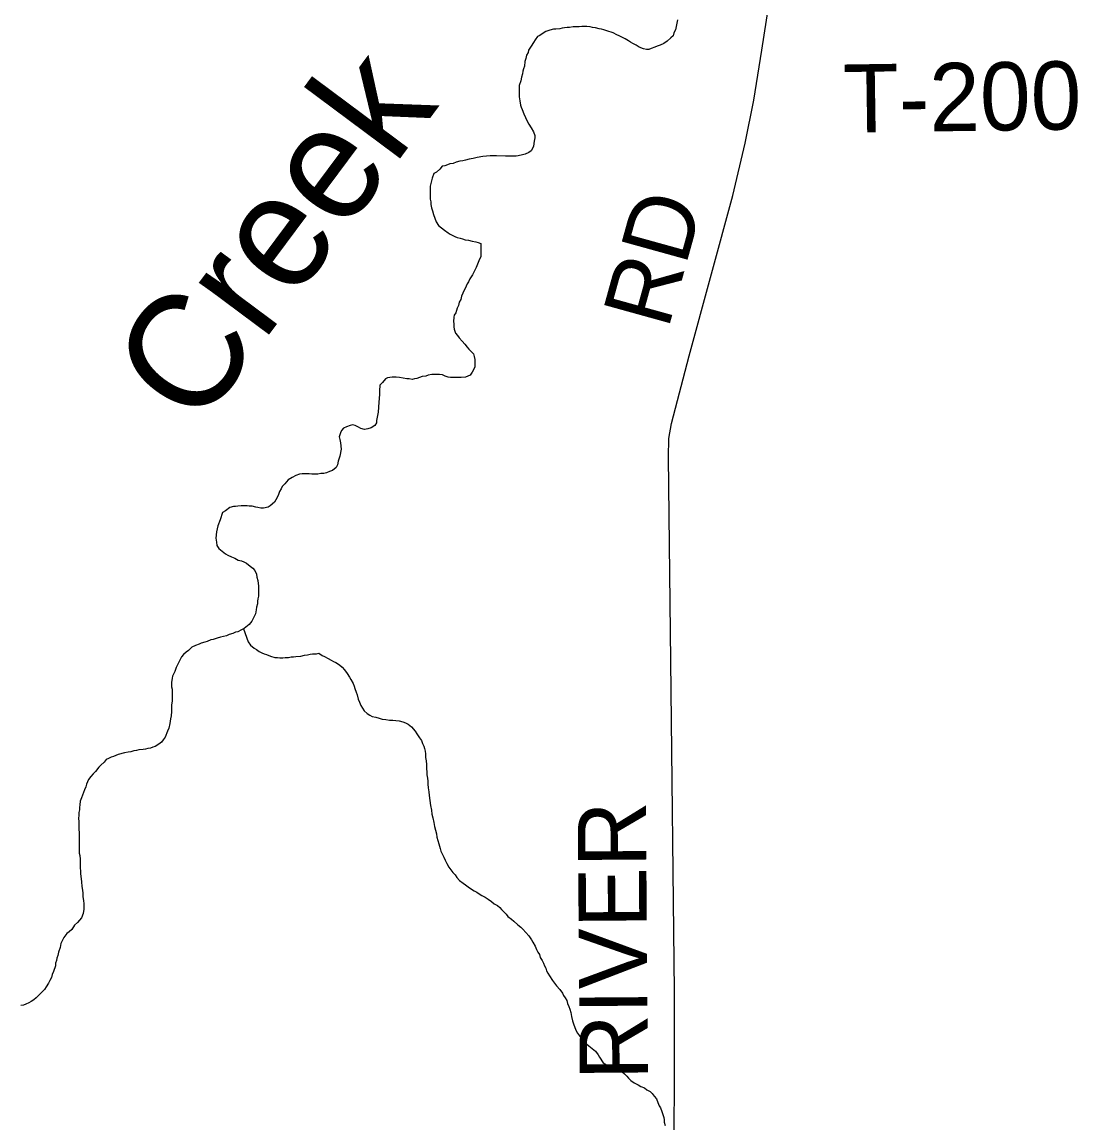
# Model space of a CAD drawing. Extents: x 0 to 34, y 0 to 22.
# Drawn here: x 3.195 to 4.075, y 18.8 to 19.717 of the extents above; entities that cross this region are included whole.
import ezdxf

# ---------------------------------------------------------------- set-up
doc = ezdxf.new("R2010")
doc.units = 0
for name, color, linetype in [('GM_X_Minor_River', 7, 'Continuous'), ('GM_X_Minor_River_Text', 7, 'Continuous'), ('GM_X_Township_Road', 7, 'Continuous'), ('GM_X_Township_Road_Text', 7, 'Continuous')]:
    doc.layers.add(name, color=color, linetype=linetype)

msp = doc.modelspace()

# ---------------------------------------------------------------- linework, layer by layer
at = {"layer": 'GM_X_Minor_River'}
for points in [[(3.74103, 19.71925), (3.73912, 19.71088), (3.73798, 19.70822), (3.73721, 19.70594), (3.73531, 19.70404), (3.73227, 19.70138), (3.72961, 19.69948), (3.72657, 19.69796), (3.72391, 19.69721), (3.722, 19.69645), (3.71896, 19.69531), (3.71706, 19.69455), (3.71516, 19.69455), (3.7125, 19.69493), (3.70908, 19.69646), (3.70643, 19.69798), (3.70377, 19.6995), (3.70187, 19.70065), (3.69997, 19.70179), (3.69731, 19.70331), (3.69503, 19.70446), (3.69238, 19.70598), (3.69048, 19.70674), (3.68744, 19.70827), (3.68554, 19.70903), (3.68364, 19.70941), (3.67946, 19.71093), (3.67756, 19.71131), (3.67566, 19.7117), (3.67262, 19.71246), (3.66997, 19.71284), (3.66807, 19.71323), (3.66541, 19.71361), (3.66313, 19.71361), (3.66123, 19.71361), (3.65895, 19.71323), (3.65629, 19.71324), (3.65401, 19.71324), (3.65097, 19.71286), (3.64907, 19.71286), (3.64679, 19.71248), (3.64489, 19.7121)], [(3.64489, 19.7121), (3.64299, 19.71172), (3.63957, 19.71135), (3.63767, 19.71135), (3.63462, 19.71059), (3.6312, 19.70945), (3.62816, 19.70755), (3.62626, 19.70603), (3.62436, 19.70527), (3.62246, 19.70261), (3.62093, 19.70033), (3.61903, 19.69729), (3.61675, 19.69387), (3.61637, 19.69197), (3.61522, 19.68969), (3.61446, 19.68703), (3.6137, 19.68437), (3.61331, 19.68056), (3.61255, 19.67828), (3.61217, 19.67638), (3.61179, 19.6741), (3.61102, 19.67144), (3.61026, 19.66839), (3.60912, 19.66459), (3.60911, 19.66003), (3.60911, 19.65737), (3.60911, 19.65508), (3.60948, 19.65166), (3.61024, 19.64824), (3.61062, 19.64634), (3.61137, 19.64443), (3.61289, 19.64101), (3.61441, 19.63797), (3.61592, 19.63416), (3.61706, 19.63226), (3.61896, 19.62921), (3.62085, 19.62579), (3.62199, 19.62274), (3.62199, 19.62084), (3.62161, 19.61818), (3.62122, 19.61628), (3.62084, 19.61362), (3.61894, 19.6102), (3.61704, 19.60868), (3.61399, 19.60716), (3.61172, 19.60678), (3.60829, 19.60602), (3.60639, 19.60564), (3.60373, 19.60565), (3.60107, 19.60565), (3.59765, 19.60565), (3.59005, 19.60604), (3.58778, 19.60604), (3.58474, 19.60604), (3.58169, 19.60566), (3.57865, 19.60529), (3.57409, 19.60453), (3.57067, 19.60377), (3.56725, 19.60302), (3.56421, 19.60226), (3.56193, 19.60188), (3.55965, 19.6015), (3.55661, 19.60074), (3.55395, 19.5996), (3.55129, 19.59923), (3.54939, 19.59847), (3.54711, 19.59771), (3.54483, 19.59733), (3.54293, 19.59467), (3.54026, 19.59239), (3.53798, 19.59125), (3.53646, 19.58744), (3.53493, 19.5806), (3.53492, 19.57452), (3.53492, 19.57186), (3.53492, 19.56995), (3.5353, 19.56767), (3.53529, 19.56539), (3.53605, 19.56273), (3.53681, 19.56006), (3.53757, 19.55702), (3.53984, 19.55093), (3.54173, 19.54789), (3.54439, 19.54598), (3.54667, 19.54408), (3.54971, 19.5418), (3.55161, 19.54065), (3.5554, 19.53875), (3.5573, 19.53799), (3.55996, 19.53723), (3.56186, 19.53684), (3.56414, 19.53608), (3.5668, 19.5357), (3.56984, 19.53494), (3.57288, 19.53417), (3.57478, 19.53379), (3.57706, 19.53303), (3.57705, 19.52618), (3.57705, 19.5239), (3.57704, 19.522), (3.57552, 19.51858)], [(3.57552, 19.51858), (3.57324, 19.51287), (3.57133, 19.50907), (3.57019, 19.50679), (3.56791, 19.50337), (3.56676, 19.50109), (3.56562, 19.49919), (3.5641, 19.49538), (3.56296, 19.49348), (3.56219, 19.49158), (3.56105, 19.48892), (3.56029, 19.48626), (3.55915, 19.48398), (3.55838, 19.48132), (3.55724, 19.47904), (3.5561, 19.47523), (3.55495, 19.47333), (3.55457, 19.47143), (3.55419, 19.46801), (3.55457, 19.46611), (3.55456, 19.46344), (3.55494, 19.46155), (3.55608, 19.45812), (3.5576, 19.45622), (3.55911, 19.45431), (3.56139, 19.45165), (3.56367, 19.44898), (3.56557, 19.4467), (3.56708, 19.4448), (3.57088, 19.44099), (3.57164, 19.43871), (3.57201, 19.43643), (3.57201, 19.43453), (3.57201, 19.42996), (3.56972, 19.42578), (3.5682, 19.42312), (3.5644, 19.4216), (3.5606, 19.42122), (3.55794, 19.42123), (3.55566, 19.42123), (3.55376, 19.42123), (3.55186, 19.42123), (3.54996, 19.42161), (3.5473, 19.42238), (3.54502, 19.42352), (3.54274, 19.4239), (3.53932, 19.42391), (3.53628, 19.42391), (3.53324, 19.42315), (3.53134, 19.42239), (3.5283, 19.42201), (3.52602, 19.42125), (3.52374, 19.42049), (3.52184, 19.42012), (3.51994, 19.41974), (3.51728, 19.42012), (3.51538, 19.42012), (3.51234, 19.42088), (3.5093, 19.42127), (3.50664, 19.42165), (3.50322, 19.42165), (3.49942, 19.4209), (3.49752, 19.42014), (3.49524, 19.41709), (3.49296, 19.41481), (3.49257, 19.41025), (3.49257, 19.40721), (3.49218, 19.40074), (3.49179, 19.39656), (3.49141, 19.39238), (3.49026, 19.38553), (3.49026, 19.38363), (3.48874, 19.38135), (3.4857, 19.37945), (3.48304, 19.37869), (3.48, 19.37794), (3.47696, 19.3787), (3.47506, 19.37984), (3.4724, 19.38136), (3.47012, 19.38175), (3.46822, 19.38137), (3.46518, 19.38023), (3.46252, 19.37909), (3.461, 19.37719), (3.46023, 19.37529), (3.45909, 19.37187), (3.45947, 19.36959), (3.46022, 19.36692), (3.4606, 19.3616), (3.45945, 19.35589), (3.45831, 19.35171), (3.45755, 19.34867), (3.4564, 19.34639), (3.45336, 19.34373), (3.45108, 19.34297), (3.44842, 19.34183), (3.44614, 19.34145), (3.44386, 19.34145), (3.4412, 19.34069), (3.43892, 19.3407), (3.43626, 19.3407)], [(3.43626, 19.3407), (3.43398, 19.34108), (3.43208, 19.34108), (3.43018, 19.34108), (3.42828, 19.34109), (3.426, 19.34071), (3.42296, 19.33957), (3.41992, 19.33805), (3.41649, 19.33615), (3.41383, 19.33273), (3.41155, 19.33045), (3.41079, 19.32855), (3.40926, 19.32627), (3.4085, 19.32399), (3.40736, 19.32133), (3.40622, 19.31943), (3.40507, 19.31753), (3.40165, 19.31449), (3.39975, 19.31334), (3.39595, 19.31259), (3.39367, 19.31259), (3.39139, 19.31297), (3.38949, 19.31336), (3.38645, 19.31412), (3.38417, 19.31412), (3.38227, 19.3145), (3.38037, 19.3145), (3.37733, 19.31451), (3.37467, 19.31413), (3.37277, 19.31375), (3.37087, 19.31375), (3.36783, 19.31299), (3.36441, 19.31033), (3.36175, 19.30881), (3.35984, 19.30273), (3.35794, 19.29779), (3.35679, 19.29284), (3.3564, 19.28752), (3.35678, 19.2841), (3.35716, 19.28144), (3.35868, 19.27877), (3.36437, 19.27458), (3.36627, 19.27344), (3.36931, 19.27192), (3.37197, 19.27077), (3.375, 19.26925), (3.37766, 19.26849), (3.37956, 19.26772), (3.38184, 19.26658), (3.38488, 19.2643), (3.38716, 19.26239), (3.38867, 19.26049), (3.39019, 19.25745), (3.39057, 19.25516), (3.39132, 19.25212), (3.3917, 19.24756), (3.3917, 19.24375), (3.39169, 19.24185), (3.39169, 19.23919), (3.39131, 19.23691), (3.39093, 19.23501), (3.39093, 19.23273), (3.39016, 19.23006), (3.38978, 19.22778), (3.38939, 19.22436), (3.38749, 19.22056), (3.38635, 19.21827), (3.38407, 19.21562), (3.37988, 19.2122), (3.3776, 19.21106), (3.37456, 19.20954), (3.37266, 19.20916), (3.37038, 19.20802), (3.36734, 19.20726), (3.36506, 19.20612), (3.36278, 19.20574), (3.36012, 19.20499), (3.35746, 19.20423), (3.35404, 19.20309), (3.35213, 19.20271), (3.34909, 19.20157), (3.34719, 19.20081), (3.34415, 19.20006), (3.34225, 19.1993), (3.33921, 19.19816), (3.33617, 19.19664), (3.33351, 19.19398), (3.3316, 19.19246), (3.32932, 19.19056), (3.3278, 19.18866), (3.32323, 19.17992), (3.32209, 19.17649), (3.32018, 19.17269), (3.3198, 19.17079), (3.31942, 19.16737), (3.31942, 19.16547), (3.31941, 19.16357), (3.31979, 19.16166), (3.31979, 19.159), (3.31979, 19.15672), (3.31978, 19.15406)], [(3.37936, 19.21193), (3.38329, 19.20116), (3.38519, 19.1985), (3.38823, 19.19584), (3.39012, 19.19469), (3.3924, 19.19317), (3.39468, 19.19203), (3.39658, 19.19126), (3.39848, 19.1905), (3.4019, 19.18936), (3.40532, 19.18821), (3.4076, 19.18821), (3.4095, 19.18783), (3.41216, 19.18783), (3.41406, 19.18821), (3.41672, 19.18821), (3.419, 19.18858), (3.42089, 19.18858), (3.4228, 19.18896), (3.42698, 19.18934), (3.43002, 19.1901), (3.43268, 19.19047), (3.43496, 19.19085), (3.43686, 19.19123), (3.44028, 19.19123), (3.44218, 19.19161), (3.44484, 19.1897), (3.44674, 19.18894), (3.44977, 19.18742), (3.45243, 19.18589), (3.45433, 19.18475), (3.45623, 19.18399), (3.45927, 19.18209), (3.46154, 19.18018), (3.46344, 19.1779), (3.46572, 19.17485), (3.46762, 19.17181), (3.46875, 19.16991), (3.47065, 19.16648), (3.47141, 19.1642), (3.47217, 19.1623), (3.4733, 19.15925), (3.47406, 19.15697), (3.47482, 19.15355), (3.47595, 19.15088), (3.47709, 19.14822), (3.47975, 19.14366), (3.4824, 19.14137), (3.48468, 19.14023), (3.48658, 19.13909), (3.48962, 19.13832), (3.49228, 19.13756), (3.49494, 19.1368), (3.49798, 19.13641), (3.50102, 19.13603), (3.50368, 19.13603), (3.50633, 19.13565), (3.509, 19.13526), (3.51203, 19.1345), (3.51431, 19.13374), (3.51659, 19.13259), (3.51925, 19.13031), (3.52229, 19.12688), (3.5238, 19.1246), (3.52608, 19.12118), (3.5276, 19.11889), (3.52836, 19.11661), (3.52949, 19.11433), (3.53025, 19.11243), (3.53063, 19.11014), (3.531, 19.10786), (3.531, 19.10482), (3.53138, 19.10216), (3.53175, 19.09911), (3.53175, 19.09531), (3.53213, 19.09303), (3.53212, 19.09037), (3.5325, 19.0877), (3.53288, 19.08504), (3.53288, 19.08276), (3.53325, 19.07971), (3.53363, 19.07629), (3.53401, 19.07325), (3.53514, 19.06488), (3.53589, 19.06108), (3.53627, 19.05765), (3.53703, 19.05461), (3.53778, 19.05081), (3.53854, 19.04738), (3.5393, 19.04434), (3.54005, 19.0413), (3.54043, 19.03863), (3.54119, 19.03559), (3.54194, 19.03293), (3.5427, 19.03103), (3.54308, 19.02912), (3.54384, 19.02684), (3.54497, 19.02456)], [(3.31978, 19.15406), (3.31978, 19.15177), (3.3194, 19.14873), (3.31939, 19.14645), (3.31939, 19.14303), (3.31901, 19.1396), (3.31863, 19.13694), (3.31824, 19.13504), (3.31786, 19.13314), (3.3171, 19.12934), (3.31595, 19.12668), (3.31405, 19.12173), (3.31253, 19.11945), (3.311, 19.11755), (3.30872, 19.11603), (3.30568, 19.11413), (3.30378, 19.11337), (3.30188, 19.11262), (3.2996, 19.11224), (3.2977, 19.11186), (3.2958, 19.11148), (3.292, 19.1111), (3.2901, 19.11073), (3.28782, 19.11035), (3.28554, 19.10959), (3.28326, 19.10921), (3.28022, 19.10883), (3.27489, 19.10731), (3.27299, 19.10655), (3.27109, 19.1058), (3.26919, 19.10504), (3.26691, 19.1039), (3.26501, 19.10314), (3.26311, 19.10086), (3.26045, 19.09858), (3.25893, 19.09668), (3.25588, 19.09326), (3.25398, 19.09136), (3.25208, 19.08908), (3.25017, 19.08642), (3.24865, 19.08262), (3.24789, 19.08033), (3.24675, 19.07805), (3.24598, 19.07577), (3.24522, 19.07349), (3.24446, 19.07121), (3.24332, 19.06855), (3.24293, 19.06551), (3.24255, 19.06322), (3.24255, 19.06132), (3.24217, 19.05904), (3.24216, 19.05676), (3.24178, 19.0541), (3.24216, 19.05143), (3.24215, 19.04801), (3.24215, 19.04497), (3.24253, 19.0423), (3.24252, 19.03964), (3.24252, 19.03584), (3.24252, 19.03242), (3.24251, 19.02975), (3.24251, 19.02519), (3.24289, 19.02329), (3.24326, 19.02025), (3.24326, 19.01797), (3.24326, 19.0153), (3.24363, 19.00808), (3.24401, 19.00389), (3.24438, 19.00123), (3.24476, 18.99743), (3.24514, 18.99438), (3.24551, 18.99172), (3.24551, 18.98868), (3.24589, 18.98563), (3.24626, 18.98297), (3.24626, 18.98031), (3.24626, 18.97841), (3.24587, 18.97499), (3.24435, 18.97118), (3.24093, 18.96738), (3.23864, 18.9651), (3.23636, 18.96168), (3.23408, 18.95978), (3.23218, 18.95826), (3.22951, 18.95484), (3.22837, 18.95218), (3.22723, 18.9499), (3.22647, 18.94648), (3.22532, 18.94268), (3.22456, 18.94001), (3.22379, 18.93773), (3.22341, 18.93583), (3.22265, 18.93355), (3.22265, 18.93127), (3.22112, 18.9267), (3.21998, 18.92404), (3.21922, 18.92176), (3.21807, 18.9191), (3.21693, 18.91682), (3.21503, 18.91378), (3.21351, 18.9115)], [(3.54497, 19.02456), (3.54611, 19.02189), (3.54725, 19.01923), (3.54877, 19.01657), (3.55028, 19.01352), (3.55218, 19.01124), (3.5537, 19.00896), (3.55559, 19.00705), (3.55711, 19.00477), (3.55939, 19.00249), (3.56243, 19.0002), (3.56433, 18.99868), (3.5666, 18.99716), (3.56926, 18.99525), (3.57154, 18.99373), (3.57382, 18.99259), (3.57572, 18.99144), (3.578, 18.98992), (3.58065, 18.9884), (3.58331, 18.98687), (3.58597, 18.98497), (3.58825, 18.98307), (3.5909, 18.98154), (3.5928, 18.98002), (3.59432, 18.97812), (3.59622, 18.97621), (3.59812, 18.97431), (3.59964, 18.97241), (3.60267, 18.97012), (3.60457, 18.9686), (3.60799, 18.96556), (3.61027, 18.96365), (3.61216, 18.96175), (3.6171, 18.95642), (3.61937, 18.95299), (3.62051, 18.95109), (3.62241, 18.94767), (3.62354, 18.94501), (3.62468, 18.94272), (3.62582, 18.94082), (3.62658, 18.93816), (3.62809, 18.93587), (3.62923, 18.93359), (3.62999, 18.93131), (3.63113, 18.92941), (3.63188, 18.92712), (3.63302, 18.92522), (3.63416, 18.92294), (3.63682, 18.91913), (3.63833, 18.91685), (3.64023, 18.91456), (3.64289, 18.91152), (3.64516, 18.90848), (3.64592, 18.90657), (3.64744, 18.90467), (3.64858, 18.90239), (3.64933, 18.9001), (3.65047, 18.89744), (3.65123, 18.89516), (3.65199, 18.8925), (3.65274, 18.88907), (3.6535, 18.88565), (3.65426, 18.88299), (3.65539, 18.87994), (3.65653, 18.87728), (3.65767, 18.87538), (3.65919, 18.87309), (3.6607, 18.87119), (3.6626, 18.86853), (3.66526, 18.86624), (3.66716, 18.86472), (3.66981, 18.86244), (3.67247, 18.86015), (3.67475, 18.85711), (3.67589, 18.8552), (3.67892, 18.85064), (3.6831, 18.84797), (3.685, 18.84721), (3.68765, 18.84645), (3.68993, 18.84569), (3.69259, 18.84416), (3.69487, 18.84302), (3.69677, 18.8415), (3.69867, 18.83959), (3.70018, 18.83769), (3.70208, 18.83579), (3.70474, 18.83388), (3.70816, 18.83236), (3.71044, 18.83084), (3.71347, 18.82969), (3.71537, 18.82817), (3.71803, 18.82665), (3.71993, 18.82512), (3.72145, 18.82284), (3.72335, 18.82056), (3.72448, 18.81751), (3.72562, 18.81485), (3.72676, 18.81295), (3.72789, 18.8099), (3.72941, 18.80496), (3.72979, 18.80305)], [(3.21351, 18.9115), (3.21084, 18.90884), (3.20666, 18.90466), (3.20476, 18.90314), (3.20248, 18.90162), (3.20058, 18.90048), (3.19791, 18.89934), (3.19601, 18.89858), (3.19373, 18.8982)], [(3.72979, 18.80305), (3.72979, 18.80115), (3.73054, 18.79849)]]:
    msp.add_lwpolyline(points, dxfattribs=at)
at = {"layer": 'GM_X_Township_Road'}
msp.add_lwpolyline([(3.73803, 18.71839), (3.73846, 18.90991), (3.73545, 19.18543), (3.73351, 19.35493), (3.73358, 19.37051), (3.73591, 19.38304), (3.75055, 19.43923), (3.78715, 19.57286), (3.79719, 19.61652), (3.80454, 19.65221), (3.81117, 19.69399), (3.81701, 19.73137)], dxfattribs=at)

# ---------------------------------------------------------------- texts
at = {"layer": 'GM_X_Minor_River_Text'}
msp.add_text('Creek', height=0.094751, rotation=53.33644, dxfattribs=at).set_placement((3.34073, 19.37656))
at = {"layer": 'GM_X_Township_Road_Text'}
for s, rotation, p in [('T-200', 0.84314, (3.87932, 19.62511)), ('RD', 74.52944, (3.733, 19.46051)), ('RIVER', 90.43716, (3.71636, 18.83634))]:
    msp.add_text(s, height=0.056818, rotation=rotation, dxfattribs=at).set_placement(p)

doc.saveas('drawing.dxf')
